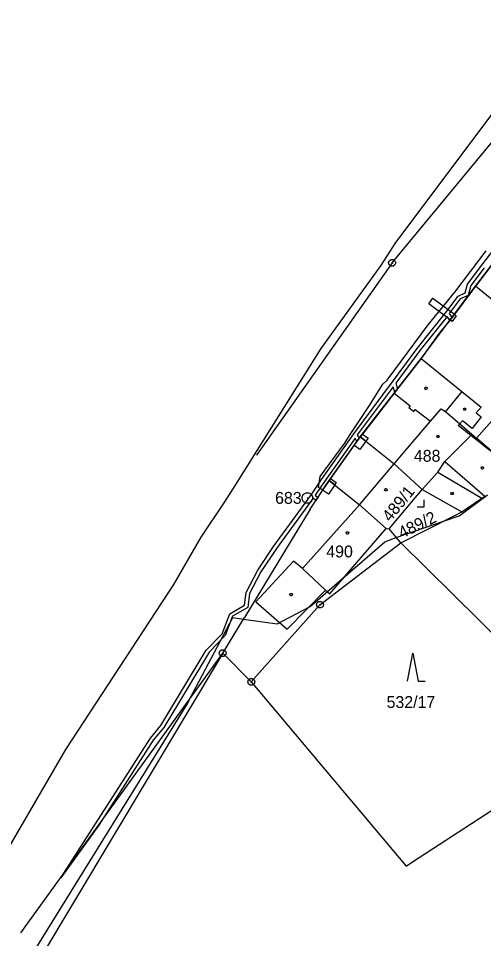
# Model space of a CAD drawing. Extents: x -759699 to -757730, y -1172308 to -1170857.
# Drawn here: x -759560 to -759493.5, y -1171878.7 to -1171747.3 of the extents above; entities that cross this region are included whole.
import ezdxf

# ---------------------------------------------------------------- set-up
doc = ezdxf.new("R2010")
doc.units = 0
for name, color, linetype in [('Vrstva 1', 7, 'Continuous'), ('Vrstva 11', 7, 'Continuous'), ('Vrstva 12', 7, 'Continuous'), ('Vrstva 13', 7, 'Continuous'), ('Vrstva 2', 7, 'Continuous'), ('Vrstva 3', 7, 'Continuous'), ('Vrstva 4', 7, 'Continuous'), ('Vrstva 5', 7, 'Continuous'), ('Vrstva 8', 7, 'Continuous')]:
    doc.layers.add(name, color=color, linetype=linetype)

msp = doc.modelspace()

# ---------------------------------------------------------------- linework, layer by layer
at = {"layer": 'Vrstva 1'}
for p, q in [((-759506.59, -1171782.21), (-759492.23, -1171764.82)), ((-759494.67, -1171785.55), (-759489.2, -1171778.33)), ((-759506.59, -1171782.21), (-759525.96, -1171809.68)), ((-759502.46, -1171795.86), (-759494.67, -1171785.55)), ((-759488.86, -1171790.32), (-759494.67, -1171785.55)), ((-759506.31, -1171800.83), (-759502.46, -1171795.86)), ((-759502.46, -1171795.86), (-759496.63, -1171800.59)), ((-759496.63, -1171800.59), (-759498.96, -1171803.46)), ((-759511.15, -1171807.06), (-759506.31, -1171800.83)), ((-759498.96, -1171803.46), (-759496.93, -1171805.21)), ((-759496.93, -1171805.21), (-759494.57, -1171807.25)), ((-759515.6, -1171813.29), (-759511.15, -1171807.06)), ((-759511.15, -1171807.06), (-759510.34, -1171807.7)), ((-759491.08, -1171810.27), (-759494.57, -1171807.25)), ((-759510.34, -1171807.7), (-759506.29, -1171810.93)), ((-759525.96, -1171809.68), (-759525.96, -1171809.68)), ((-759506.29, -1171810.93), (-759502.31, -1171814.57)), ((-759518.31, -1171817.39), (-759515.6, -1171813.29)), ((-759515.6, -1171813.29), (-759511.27, -1171816.77)), ((-759507.04, -1171820.23), (-759502.31, -1171814.57)), ((-759502.31, -1171814.57), (-759496.63, -1171817.76)), ((-759496.63, -1171817.76), (-759493.78, -1171815.83)), ((-759493.78, -1171815.83), (-759493.35, -1171815.54)), ((-759518.31, -1171817.39), (-759527.68, -1171832.88)), ((-759511.27, -1171816.77), (-759507.47, -1171820.14)), ((-759497.75, -1171818.34), (-759496.63, -1171817.76)), ((-759505.36, -1171822.23), (-759497.75, -1171818.34)), ((-759507.47, -1171820.14), (-759507.04, -1171820.23)), ((-759505.36, -1171822.23), (-759507.04, -1171820.23)), ((-759516.91, -1171831.05), (-759505.36, -1171822.23)), ((-759505.36, -1171822.23), (-759476.05, -1171851.21)), ((-759526.72, -1171842.08), (-759516.91, -1171831.05)), ((-759530.79, -1171837.99), (-759527.68, -1171832.88)), ((-759530.79, -1171837.99), (-759568.11, -1171900.29)), ((-759559.62, -1171877.94), (-759530.79, -1171837.99)), ((-759530.79, -1171837.99), (-759526.72, -1171842.08)), ((-759526.72, -1171842.08), (-759504.61, -1171868.38)), ((-759503.69, -1171867.78), (-759487.07, -1171856.95)), ((-759504.61, -1171868.38), (-759503.69, -1171867.78)), ((-759559.62, -1171877.94), (-759559.62, -1171877.94))]:
    msp.add_line(p, q, dxfattribs=at)
at = {"layer": 'Vrstva 11'}
for p, q in [((-759482.13, -1171747.3), (-759506.1, -1171779.29)), ((-759506.1, -1171779.29), (-759508.24, -1171782.66)), ((-759508.24, -1171782.66), (-759516.8, -1171794.45)), ((-759516.8, -1171794.45), (-759529.1, -1171814.1)), ((-759529.1, -1171814.1), (-759530.52, -1171816.36)), ((-759530.52, -1171816.36), (-759533.94, -1171821.41)), ((-759497.02, -1171818.33), (-759492.98, -1171815.35)), ((-759506, -1171821.47), (-759499.27, -1171819.12)), ((-759499.27, -1171819.12), (-759497.02, -1171818.33)), ((-759533.94, -1171821.41), (-759537.81, -1171828.16)), ((-759507.65, -1171822.05), (-759506, -1171821.47)), ((-759518.32, -1171831.28), (-759507.65, -1171822.05)), ((-759537.81, -1171828.16), (-759553.23, -1171851.75)), ((-759523, -1171833.79), (-759518.32, -1171831.28)), ((-759535.43, -1171844.42), (-759529.35, -1171832.89)), ((-759529.35, -1171832.89), (-759527.82, -1171833.1)), ((-759527.82, -1171833.1), (-759523, -1171833.79)), ((-759569.24, -1171899.05), (-759535.8, -1171845.12)), ((-759535.8, -1171845.12), (-759535.43, -1171844.42)), ((-759553.23, -1171851.75), (-759561.81, -1171866.5))]:
    msp.add_line(p, q, dxfattribs=at)
at = {"layer": 'Vrstva 12'}
for p, q in [((-759501.12, -1171804.83), (-759499.61, -1171803.05)), ((-759499.61, -1171803.05), (-759498.96, -1171803.46)), ((-759498.96, -1171803.46), (-759496.93, -1171805.21)), ((-759506.29, -1171810.93), (-759501.12, -1171804.83)), ((-759497.16, -1171805.47), (-759496.93, -1171805.21)), ((-759495.36, -1171806.9), (-759497.16, -1171805.47)), ((-759499.07, -1171810.57), (-759495.36, -1171806.9)), ((-759511.27, -1171816.77), (-759506.29, -1171810.93)), ((-759506.29, -1171810.93), (-759502.31, -1171814.57)), ((-759506.29, -1171810.93), (-759502.31, -1171814.57)), ((-759500.09, -1171812.12), (-759499.07, -1171810.57)), ((-759502.31, -1171814.57), (-759500.09, -1171812.12)), ((-759507.04, -1171820.23), (-759502.31, -1171814.57)), ((-759511.27, -1171816.77), (-759519.41, -1171825.89)), ((-759511.27, -1171816.77), (-759507.47, -1171820.14)), ((-759511.27, -1171816.77), (-759507.47, -1171820.14)), ((-759515.49, -1171829.5), (-759507.47, -1171820.14)), ((-759507.47, -1171820.14), (-759507.04, -1171820.23)), ((-759516.1, -1171828.95), (-759519.41, -1171825.89)), ((-759516.1, -1171828.95), (-759515.49, -1171829.5))]:
    msp.add_line(p, q, dxfattribs=at)
at = {"layer": 'Vrstva 13'}
for p, q in [((-759493.63, -1171782.34), (-759485.86, -1171772.1)), ((-759497.62, -1171786.39), (-759493.18, -1171780.51)), ((-759495.83, -1171785.25), (-759493.63, -1171782.34)), ((-759493.44, -1171782.93), (-759495.37, -1171785.47)), ((-759492.3, -1171782.45), (-759494.67, -1171785.55)), ((-759494.67, -1171785.55), (-759498.19, -1171790.23)), ((-759496.16, -1171786.52), (-759495.83, -1171785.25)), ((-759495.37, -1171785.47), (-759495.74, -1171786.88)), ((-759501.44, -1171791.05), (-759497.62, -1171786.39)), ((-759501.37, -1171788.05), (-759500.77, -1171787.25)), ((-759500.77, -1171787.25), (-759497.71, -1171789.57)), ((-759498.94, -1171789.31), (-759497.19, -1171786.97)), ((-759496.87, -1171787.37), (-759498.44, -1171789.47)), ((-759497.19, -1171786.97), (-759496.16, -1171786.52)), ((-759495.74, -1171786.88), (-759496.87, -1171787.37)), ((-759498.31, -1171790.37), (-759501.37, -1171788.05)), ((-759503.01, -1171794.43), (-759498.94, -1171789.31)), ((-759498.76, -1171789.89), (-759502.62, -1171794.73)), ((-759498.37, -1171790.45), (-759498.76, -1171789.89)), ((-759498.44, -1171789.47), (-759498.05, -1171790.03)), ((-759498.05, -1171790.03), (-759498.37, -1171790.45)), ((-759498.31, -1171790.37), (-759497.71, -1171789.57)), ((-759497.71, -1171789.57), (-759498.31, -1171790.37)), ((-759497.43, -1171789.78), (-759498.03, -1171790.58)), ((-759497.71, -1171789.57), (-759497.43, -1171789.78)), ((-759507.32, -1171798.99), (-759501.44, -1171791.05)), ((-759498.19, -1171790.23), (-759499.86, -1171792.27)), ((-759498.03, -1171790.58), (-759498.31, -1171790.37)), ((-759499.86, -1171792.27), (-759502.46, -1171795.86)), ((-759506.55, -1171799.21), (-759503.01, -1171794.43)), ((-759502.62, -1171794.73), (-759506.07, -1171799.41)), ((-759502.46, -1171795.86), (-759506.31, -1171800.83)), ((-759512.07, -1171806.63), (-759506.55, -1171799.21)), ((-759507.93, -1171799.54), (-759507.32, -1171798.99)), ((-759506.07, -1171799.41), (-759505.83, -1171800.21)), ((-759506.44, -1171799.91), (-759511.57, -1171806.79)), ((-759509.91, -1171802.74), (-759507.93, -1171799.54)), ((-759506.21, -1171800.7), (-759506.44, -1171799.91)), ((-759505.83, -1171800.21), (-759506.21, -1171800.7)), ((-759506.31, -1171800.83), (-759510.85, -1171806.67)), ((-759512.59, -1171806.72), (-759509.91, -1171802.74)), ((-759516.7, -1171813.16), (-759512.07, -1171806.63)), ((-759511.89, -1171807.24), (-759516.28, -1171813.44)), ((-759513.41, -1171808.02), (-759512.59, -1171806.72)), ((-759511.15, -1171807.06), (-759512.02, -1171808.28)), ((-759512.02, -1171808.28), (-759511.15, -1171807.06)), ((-759511.62, -1171807.72), (-759511.89, -1171807.24)), ((-759511.3, -1171807.27), (-759511.62, -1171807.72)), ((-759511.57, -1171806.79), (-759511.3, -1171807.27)), ((-759510.85, -1171806.67), (-759511.15, -1171807.06)), ((-759511.15, -1171807.06), (-759510.85, -1171806.67)), ((-759510.34, -1171807.7), (-759511.15, -1171807.06)), ((-759511.15, -1171807.06), (-759510.34, -1171807.7)), ((-759510.85, -1171806.67), (-759510.02, -1171807.26)), ((-759510.02, -1171807.26), (-759510.34, -1171807.7)), ((-759516.87, -1171812.74), (-759513.41, -1171808.02)), ((-759512.02, -1171808.28), (-759515.42, -1171813.03)), ((-759512.01, -1171808.29), (-759512.02, -1171808.28)), ((-759511.2, -1171808.87), (-759512.01, -1171808.29)), ((-759510.34, -1171807.7), (-759511.2, -1171808.87)), ((-759518.11, -1171815.3), (-759516.7, -1171813.16)), ((-759516.28, -1171813.44), (-759517.57, -1171815.4)), ((-759517.1, -1171814.31), (-759516.87, -1171812.74)), ((-759515.6, -1171813.29), (-759516.53, -1171814.69)), ((-759516.53, -1171814.69), (-759515.6, -1171813.29)), ((-759515.42, -1171813.03), (-759515.6, -1171813.29)), ((-759515.6, -1171813.29), (-759515.42, -1171813.03)), ((-759515.6, -1171813.29), (-759514.8, -1171813.94)), ((-759514.8, -1171813.94), (-759515.6, -1171813.29)), ((-759515.42, -1171813.03), (-759514.57, -1171813.6)), ((-759514.57, -1171813.6), (-759514.8, -1171813.94)), ((-759516.53, -1171814.69), (-759517.1, -1171814.31)), ((-759515.68, -1171815.26), (-759516.53, -1171814.69)), ((-759514.8, -1171813.94), (-759515.68, -1171815.26)), ((-759523.53, -1171822.73), (-759518.11, -1171815.3)), ((-759517.86, -1171815.81), (-759523.12, -1171823.02)), ((-759517.48, -1171816.14), (-759517.86, -1171815.81)), ((-759517.57, -1171815.4), (-759517.2, -1171815.72)), ((-759517.2, -1171815.72), (-759517.48, -1171816.14)), ((-759525.8, -1171826.09), (-759523.53, -1171822.73)), ((-759523.12, -1171823.02), (-759525.37, -1171826.35)), ((-759527.45, -1171829.28), (-759525.8, -1171826.09)), ((-759525.37, -1171826.35), (-759526.97, -1171829.43)), ((-759527.67, -1171831.13), (-759527.45, -1171829.28)), ((-759526.97, -1171829.43), (-759527.2, -1171831.44)), ((-759529.8, -1171832.34), (-759527.67, -1171831.13)), ((-759527.2, -1171831.44), (-759529.4, -1171832.68)), ((-759530.87, -1171835.19), (-759529.8, -1171832.34)), ((-759529.4, -1171832.68), (-759530.44, -1171835.46)), ((-759533.15, -1171837.53), (-759530.87, -1171835.19)), ((-759530.44, -1171835.46), (-759532.75, -1171837.83)), ((-759539.62, -1171848.31), (-759533.15, -1171837.53)), ((-759532.75, -1171837.83), (-759539.21, -1171848.6)), ((-759541.11, -1171850.11), (-759539.62, -1171848.31)), ((-759539.21, -1171848.6), (-759540.71, -1171850.41)), ((-759553.94, -1171870.07), (-759541.11, -1171850.11)), ((-759540.71, -1171850.41), (-759548.5, -1171862.54)), ((-759548.5, -1171862.54), (-759553.94, -1171870.07))]:
    msp.add_line(p, q, dxfattribs=at)
at = {"layer": 'Vrstva 3'}
for points in [[(-759503.02, -1171817.07), (-759502.02, -1171817.07), (-759502.02, -1171816.07)], [(-759504.4, -1171841.96), (-759503.65, -1171837.96), (-759502.9, -1171841.96), (-759501.9, -1171841.96)]]:
    msp.add_lwpolyline(points, dxfattribs=at)
at = {"layer": 'Vrstva 4'}
for p, q in [((-759496.63, -1171800.59), (-759493.89, -1171802.82)), ((-759506.31, -1171800.83), (-759504.02, -1171802.62)), ((-759489.93, -1171801.99), (-759494.57, -1171807.25)), ((-759504.02, -1171802.62), (-759504.22, -1171802.87)), ((-759504.22, -1171802.87), (-759503.5, -1171803.43)), ((-759503.5, -1171803.43), (-759503.3, -1171803.18)), ((-759503.3, -1171803.18), (-759501.12, -1171804.83)), ((-759501.12, -1171804.83), (-759499.61, -1171803.05)), ((-759499.61, -1171803.05), (-759498.96, -1171803.46)), ((-759493.89, -1171802.82), (-759494.6, -1171803.62)), ((-759493.86, -1171804.22), (-759495.17, -1171805.9)), ((-759494.6, -1171803.62), (-759493.86, -1171804.22)), ((-759506.29, -1171810.93), (-759501.12, -1171804.83)), ((-759497.16, -1171805.47), (-759496.93, -1171805.21)), ((-759495.36, -1171806.9), (-759497.16, -1171805.47)), ((-759496.54, -1171804.76), (-759496.93, -1171805.21)), ((-759495.17, -1171805.9), (-759496.54, -1171804.76)), ((-759499.07, -1171810.57), (-759495.36, -1171806.9)), ((-759491.08, -1171810.27), (-759495.36, -1171806.9)), ((-759511.27, -1171816.77), (-759506.29, -1171810.93)), ((-759500.09, -1171812.12), (-759499.07, -1171810.57)), ((-759499.07, -1171810.57), (-759493.35, -1171815.54)), ((-759502.31, -1171814.57), (-759500.09, -1171812.12)), ((-759500.09, -1171812.12), (-759493.78, -1171815.83)), ((-759511.27, -1171816.77), (-759519.41, -1171825.89)), ((-759515.49, -1171829.5), (-759507.47, -1171820.14)), ((-759520.69, -1171824.85), (-759526.05, -1171830.63)), ((-759519.41, -1171825.89), (-759520.69, -1171824.85)), ((-759516.1, -1171828.95), (-759519.41, -1171825.89)), ((-759521.59, -1171834.54), (-759516.1, -1171828.95)), ((-759516.1, -1171828.95), (-759515.49, -1171829.5)), ((-759526.05, -1171830.63), (-759521.59, -1171834.54))]:
    msp.add_line(p, q, dxfattribs=at)
at = {"layer": 'Vrstva 5'}
for points in [[(-759501.68, -1171799.99), (-759501.59, -1171800.14), (-759501.68, -1171800.29), (-759501.86, -1171800.29), (-759501.95, -1171800.14), (-759501.86, -1171799.99)], [(-759496.15, -1171802.98), (-759496.06, -1171803.13), (-759496.15, -1171803.28), (-759496.33, -1171803.28), (-759496.42, -1171803.13), (-759496.33, -1171802.98)], [(-759499.95, -1171806.87), (-759499.86, -1171807.02), (-759499.95, -1171807.17), (-759500.13, -1171807.17), (-759500.22, -1171807.02), (-759500.13, -1171806.87)], [(-759493.63, -1171811.37), (-759493.54, -1171811.52), (-759493.63, -1171811.67), (-759493.81, -1171811.67), (-759493.9, -1171811.52), (-759493.81, -1171811.37)], [(-759507.42, -1171814.47), (-759507.33, -1171814.62), (-759507.42, -1171814.77), (-759507.6, -1171814.77), (-759507.69, -1171814.62), (-759507.6, -1171814.47)], [(-759497.93, -1171815.02), (-759497.84, -1171815.17), (-759497.93, -1171815.32), (-759498.11, -1171815.32), (-759498.2, -1171815.17), (-759498.11, -1171815.02)], [(-759512.89, -1171820.65), (-759512.8, -1171820.8), (-759512.89, -1171820.95), (-759513.07, -1171820.95), (-759513.16, -1171820.8), (-759513.07, -1171820.65)], [(-759520.93, -1171829.46), (-759520.84, -1171829.61), (-759520.93, -1171829.76), (-759521.11, -1171829.76), (-759521.2, -1171829.61), (-759521.11, -1171829.46)]]:
    msp.add_lwpolyline(points, close=True, dxfattribs=at)
at = {"layer": 'Vrstva 8'}
for p, q in [((-759506.71, -1171782.21), (-759506.47, -1171782.21)), ((-759518.75, -1171815.79), (-759518.65, -1171815.79)), ((-759517.03, -1171831.05), (-759516.79, -1171831.05)), ((-759530.91, -1171837.99), (-759530.67, -1171837.99)), ((-759526.84, -1171842.08), (-759526.6, -1171842.08))]:
    msp.add_line(p, q, dxfattribs=at)
for points in [[(-759506.44, -1171781.73), (-759506.19, -1171781.91), (-759506.09, -1171782.2), (-759506.19, -1171782.49), (-759506.44, -1171782.67), (-759506.75, -1171782.67), (-759507, -1171782.49), (-759507.1, -1171782.2), (-759507, -1171781.91), (-759506.75, -1171781.73)], [(-759518.51, -1171815.07), (-759518.17, -1171815.26), (-759517.98, -1171815.6), (-759517.98, -1171815.99), (-759518.17, -1171816.33), (-759518.51, -1171816.52), (-759518.9, -1171816.52), (-759519.24, -1171816.33), (-759519.43, -1171815.99), (-759519.43, -1171815.6), (-759519.24, -1171815.26), (-759518.9, -1171815.07)], [(-759516.76, -1171830.57), (-759516.51, -1171830.75), (-759516.41, -1171831.04), (-759516.51, -1171831.33), (-759516.76, -1171831.51), (-759517.07, -1171831.51), (-759517.32, -1171831.33), (-759517.42, -1171831.04), (-759517.32, -1171830.75), (-759517.07, -1171830.57)], [(-759530.64, -1171837.51), (-759530.39, -1171837.69), (-759530.29, -1171837.98), (-759530.39, -1171838.27), (-759530.64, -1171838.45), (-759530.95, -1171838.45), (-759531.2, -1171838.27), (-759531.3, -1171837.98), (-759531.2, -1171837.69), (-759530.95, -1171837.51)], [(-759526.57, -1171841.6), (-759526.32, -1171841.78), (-759526.22, -1171842.07), (-759526.32, -1171842.36), (-759526.57, -1171842.54), (-759526.88, -1171842.54), (-759527.13, -1171842.36), (-759527.23, -1171842.07), (-759527.13, -1171841.78), (-759526.88, -1171841.6)]]:
    msp.add_lwpolyline(points, close=True, dxfattribs=at)

# ---------------------------------------------------------------- texts
at = {"layer": 'Vrstva 2'}
for s, p in [('488', (-759503.491, -1171810.63)), ('490', (-759516.001, -1171824.29)), ('532/17', (-759507.392, -1171845.8))]:
    msp.add_text(s, height=1.7, dxfattribs=at).set_placement(p)
for s, rotation, p in [('489/1', 50.64947, (-759506.873, -1171819.326)), ('489/2', 25.95499, (-759505.217, -1171821.637))]:
    msp.add_text(s, height=1.7, rotation=rotation, dxfattribs=at).set_placement(p)
at = {"layer": 'Vrstva 8'}
msp.add_text('683', height=1.7, dxfattribs=at).set_placement((-759523.314, -1171816.64))

doc.saveas('drawing.dxf')
